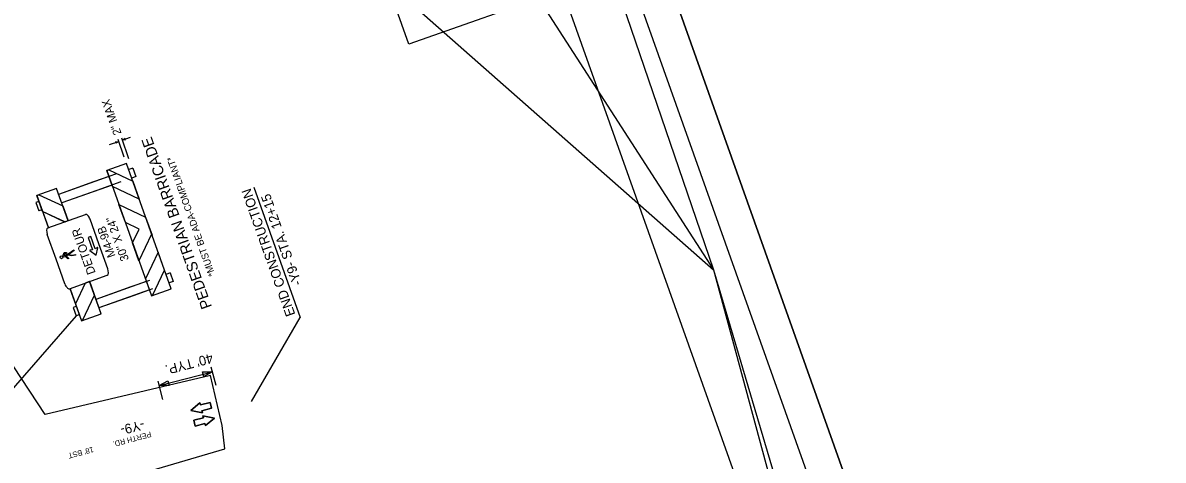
# Model space of a CAD drawing. Extents: x 1615843 to 1618439, y 899470 to 903922.
# Drawn here: x 1616617 to 1617445, y 902993 to 903311 of the extents above; entities that cross this region are included whole.
import ezdxf

# ---------------------------------------------------------------- set-up
doc = ezdxf.new("R2010")
doc.units = 0
for name, color, linetype in [('Default', 7, 'Continuous'), ('DEV BORDER CELL', 7, 'Continuous'), ('DEV DIRECTION OF TRAFFIC FLOW ARROW CELL', 7, 'Continuous'), ('DEV PED BARRICADE SECTION VIEW CELL', 7, 'Continuous'), ('GS M4-9b CELL', 7, 'Continuous'), ('Prop DSN Text', 7, 'Continuous'), ('Prop Horizontal Alignment Tick Label', 7, 'Continuous'), ('Scratch_Level_0', 7, 'Continuous'), ('Scratch_Level_5', 7, 'Continuous'), ('Sheet Clip Boundary CELL', 7, 'Continuous'), ('Sheet Plot Border Outside CELL', 7, 'Continuous'), ('Text', 7, 'Continuous')]:
    doc.layers.add(name, color=color, linetype=linetype)

msp = doc.modelspace()

# ---------------------------------------------------------------- linework, layer by layer
at = {"layer": 'Default'}
msp.add_line((1616655.34, 903097.86), (1616587.39, 903020.2), dxfattribs=at)
at = {"layer": 'DEV BORDER CELL'}
msp.add_lwpolyline([(1615874.87, 903538.12), (1616377.33, 902124.77), (1617366.67, 902476.49), (1616864.22, 903889.84)], close=True, dxfattribs=at)
at = {"layer": 'DEV DIRECTION OF TRAFFIC FLOW ARROW CELL'}
for p, q in [((1616745.15, 903034.59), (1616738.54, 903029.14)), ((1616738.54, 903029.14), (1616745.15, 903034.59)), ((1616738.54, 903029.14), (1616746.96, 903027.52)), ((1616746.96, 903027.52), (1616738.54, 903029.14)), ((1616745.52, 903033.16), (1616745.15, 903034.59)), ((1616745.15, 903034.59), (1616745.52, 903033.16)), ((1616752.49, 903034.95), (1616745.52, 903033.16)), ((1616745.52, 903033.16), (1616752.49, 903034.95)), ((1616746.59, 903028.95), (1616753.57, 903030.73)), ((1616753.57, 903030.73), (1616746.59, 903028.95)), ((1616746.96, 903027.52), (1616746.59, 903028.95)), ((1616746.59, 903028.95), (1616746.96, 903027.52)), ((1616753.57, 903030.73), (1616752.49, 903034.95)), ((1616752.49, 903034.95), (1616753.57, 903030.73)), ((1616747.67, 903023.85), (1616740.69, 903022.07)), ((1616740.69, 903022.07), (1616747.67, 903023.85)), ((1616740.69, 903022.07), (1616741.77, 903017.86)), ((1616741.77, 903017.86), (1616740.69, 903022.07)), ((1616741.77, 903017.86), (1616748.75, 903019.64)), ((1616748.75, 903019.64), (1616741.77, 903017.86)), ((1616755.72, 903023.67), (1616747.3, 903025.28)), ((1616747.3, 903025.28), (1616747.67, 903023.85)), ((1616747.67, 903023.85), (1616747.3, 903025.28)), ((1616747.3, 903025.28), (1616755.72, 903023.67)), ((1616748.75, 903019.64), (1616749.11, 903018.21)), ((1616749.11, 903018.21), (1616748.75, 903019.64)), ((1616749.11, 903018.21), (1616755.72, 903023.67)), ((1616755.72, 903023.67), (1616749.11, 903018.21))]:
    msp.add_line(p, q, dxfattribs=at)
at = {"layer": 'DEV PED BARRICADE SECTION VIEW CELL'}
for p, q in [((1616693.6, 903212.14), (1616688.33, 903226.96)), ((1616693.6, 903212.14), (1616688.33, 903226.96)), ((1616688.8, 903225.65), (1616694.79, 903227.78)), ((1616688.8, 903225.65), (1616694.79, 903227.78)), ((1616688.8, 903225.65), (1616690.81, 903226.99)), ((1616688.8, 903225.65), (1616690.81, 903226.99)), ((1616688.8, 903225.65), (1616690.81, 903226.99)), ((1616688.8, 903225.65), (1616690.81, 903226.99)), ((1616690.81, 903226.99), (1616690.45, 903226.24)), ((1616690.81, 903226.99), (1616690.45, 903226.24)), ((1616690.81, 903226.99), (1616690.45, 903226.24)), ((1616690.81, 903226.99), (1616690.45, 903226.24)), ((1616679.53, 903222.35), (1616686.16, 903224.71)), ((1616679.53, 903222.35), (1616686.16, 903224.71)), ((1616683.75, 903224.48), (1616686.16, 903224.71)), ((1616683.75, 903224.48), (1616686.16, 903224.71)), ((1616683.75, 903224.48), (1616686.16, 903224.71)), ((1616683.75, 903224.48), (1616686.16, 903224.71)), ((1616684.5, 903224.12), (1616683.75, 903224.48)), ((1616684.5, 903224.12), (1616683.75, 903224.48)), ((1616684.5, 903224.12), (1616683.75, 903224.48)), ((1616684.5, 903224.12), (1616683.75, 903224.48)), ((1616686.16, 903224.71), (1616684.14, 903223.37)), ((1616686.16, 903224.71), (1616684.14, 903223.37)), ((1616686.16, 903224.71), (1616684.14, 903223.37)), ((1616686.16, 903224.71), (1616684.14, 903223.37)), ((1616684.14, 903223.37), (1616684.5, 903224.12)), ((1616684.14, 903223.37), (1616684.5, 903224.12)), ((1616684.14, 903223.37), (1616684.5, 903224.12)), ((1616684.14, 903223.37), (1616684.5, 903224.12)), ((1616690.2, 903213.33), (1616685.69, 903226.02)), ((1616690.2, 903213.33), (1616685.69, 903226.02)), ((1616691.2, 903225.88), (1616688.8, 903225.65)), ((1616691.2, 903225.88), (1616688.8, 903225.65)), ((1616691.2, 903225.88), (1616688.8, 903225.65)), ((1616691.2, 903225.88), (1616688.8, 903225.65)), ((1616690.45, 903226.24), (1616691.2, 903225.88)), ((1616690.45, 903226.24), (1616691.2, 903225.88)), ((1616690.45, 903226.24), (1616691.2, 903225.88)), ((1616690.45, 903226.24), (1616691.2, 903225.88)), ((1616691.88, 903208.61), (1616677.58, 903203.53)), ((1616691.88, 903208.61), (1616677.58, 903203.53)), ((1616677.58, 903203.53), (1616709.98, 903112.41)), ((1616681.7, 903191.94), (1616677.58, 903203.53)), ((1616677.58, 903203.53), (1616709.98, 903112.41)), ((1616681.7, 903191.94), (1616677.58, 903203.53)), ((1616724.27, 903117.49), (1616691.88, 903208.61)), ((1616724.27, 903117.49), (1616691.88, 903208.61)), ((1616696.51, 903205.38), (1616693.42, 903204.28)), ((1616696.51, 903205.38), (1616693.42, 903204.28)), ((1616696.51, 903205.38), (1616698.71, 903199.19)), ((1616696.51, 903205.38), (1616698.71, 903199.19)), ((1616679.12, 903199.2), (1616642.55, 903186.2)), ((1616667.98, 903195.24), (1616642.55, 903186.2)), ((1616684.68, 903201.17), (1616667.98, 903195.24)), ((1616687.75, 903195.3), (1616670.18, 903189.05)), ((1616698.71, 903199.19), (1616695.62, 903198.09)), ((1616698.71, 903199.19), (1616695.62, 903198.09)), ((1616696.42, 903195.85), (1616701.08, 903182.73)), ((1616696.42, 903195.85), (1616701.08, 903182.73)), ((1616641.01, 903190.53), (1616626.71, 903185.45)), ((1616641.01, 903190.53), (1616626.71, 903185.45)), ((1616630.83, 903173.86), (1616626.71, 903185.45)), ((1616626.71, 903185.45), (1616635.1, 903161.86)), ((1616626.71, 903185.45), (1616635.14, 903161.74)), ((1616630.83, 903173.86), (1616626.71, 903185.45)), ((1616649.36, 903167.05), (1616641.01, 903190.53)), ((1616649.4, 903166.93), (1616641.01, 903190.53)), ((1616681.32, 903193.01), (1616644.75, 903180.01)), ((1616670.18, 903189.05), (1616644.75, 903180.01)), ((1616701.08, 903182.73), (1616681.7, 903191.94)), ((1616701.08, 903182.73), (1616681.7, 903191.94)), ((1616628.25, 903181.12), (1616626.03, 903180.32)), ((1616628.25, 903181.12), (1616626.03, 903180.32)), ((1616626.03, 903180.32), (1616628.23, 903174.14)), ((1616626.03, 903180.32), (1616628.23, 903174.14)), ((1616691.03, 903165.7), (1616686.37, 903178.82)), ((1616686.37, 903178.82), (1616705.74, 903169.61)), ((1616691.03, 903165.7), (1616686.37, 903178.82)), ((1616686.37, 903178.82), (1616705.74, 903169.61)), ((1616630.45, 903174.93), (1616628.23, 903174.14)), ((1616630.45, 903174.93), (1616628.23, 903174.14)), ((1616646.95, 903166.2), (1616630.83, 903173.86)), ((1616647.11, 903166.12), (1616630.83, 903173.86)), ((1616705.74, 903169.61), (1616710.41, 903156.49)), ((1616705.74, 903169.61), (1616710.41, 903156.49)), ((1616700.93, 903161), (1616691.03, 903165.7)), ((1616700.93, 903161), (1616691.03, 903165.7)), ((1616696.22, 903151.1), (1616700.93, 903161)), ((1616696.22, 903151.1), (1616700.93, 903161)), ((1616710.1, 903157.36), (1616700.89, 903137.98)), ((1616710.1, 903157.36), (1616700.89, 903137.98)), ((1616700.89, 903137.98), (1616696.22, 903151.1)), ((1616700.89, 903137.98), (1616696.22, 903151.1)), ((1616714.76, 903144.24), (1616705.55, 903124.86)), ((1616714.76, 903144.24), (1616705.55, 903124.86)), ((1616719.43, 903131.12), (1616714.76, 903144.24)), ((1616719.43, 903131.12), (1616714.76, 903144.24)), ((1616723.63, 903129.11), (1616720.53, 903128.01)), ((1616723.63, 903129.11), (1616720.53, 903128.01)), ((1616723.63, 903129.11), (1616725.83, 903122.92)), ((1616723.63, 903129.11), (1616725.83, 903122.92)), ((1616661.79, 903121.72), (1616654.68, 903106.78)), ((1616661.71, 903121.56), (1616654.68, 903106.78)), ((1616673.4, 903099.4), (1616665.06, 903122.88)), ((1616673.4, 903099.4), (1616665.1, 903122.77)), ((1616706.24, 903122.93), (1616669.66, 903109.92)), ((1616695.1, 903118.97), (1616669.66, 903109.92)), ((1616708.45, 903123.71), (1616695.1, 903118.97)), ((1616705.55, 903124.86), (1616709.98, 903112.41)), ((1616705.55, 903124.86), (1616709.98, 903112.41)), ((1616725.83, 903122.92), (1616722.73, 903121.82)), ((1616725.83, 903122.92), (1616722.73, 903121.82)), ((1616650.72, 903117.91), (1616659.11, 903094.32)), ((1616650.8, 903117.68), (1616659.11, 903094.32)), ((1616708.44, 903116.74), (1616671.86, 903103.74)), ((1616697.3, 903112.78), (1616671.86, 903103.74)), ((1616710.74, 903117.56), (1616697.3, 903112.78)), ((1616709.98, 903112.41), (1616724.27, 903117.49)), ((1616709.98, 903112.41), (1616724.27, 903117.49)), ((1616724.09, 903118), (1616723.76, 903117.31)), ((1616724.09, 903118), (1616723.76, 903117.31)), ((1616724.27, 903117.49), (1616724.09, 903118)), ((1616724.27, 903117.49), (1616724.09, 903118)), ((1616655.37, 903104.84), (1616653.14, 903104.05)), ((1616655.37, 903104.84), (1616653.14, 903104.05)), ((1616653.14, 903104.05), (1616655.34, 903097.86)), ((1616653.14, 903104.05), (1616655.34, 903097.86)), ((1616654.68, 903106.78), (1616659.11, 903094.32)), ((1616654.68, 903106.78), (1616659.11, 903094.32)), ((1616657.57, 903098.65), (1616655.34, 903097.86)), ((1616657.57, 903098.65), (1616655.34, 903097.86)), ((1616659.11, 903094.32), (1616673.4, 903099.4)), ((1616659.11, 903094.32), (1616673.4, 903099.4)), ((1616673.22, 903099.91), (1616672.89, 903099.22)), ((1616673.22, 903099.91), (1616672.89, 903099.22)), ((1616673.4, 903099.4), (1616673.22, 903099.91)), ((1616673.4, 903099.4), (1616673.22, 903099.91))]:
    msp.add_line(p, q, dxfattribs=at)
for points in [[(1616677.58, 903203.53), (1616679.11, 903204.08), (1616696.42, 903195.85)], [(1616677.58, 903203.53), (1616679.11, 903204.08), (1616696.42, 903195.85)], [(1616626.71, 903185.45), (1616628.24, 903185.99), (1616645.55, 903177.77)], [(1616626.71, 903185.45), (1616628.24, 903185.99), (1616645.55, 903177.77)], [(1616645.55, 903177.77), (1616649.36, 903167.05), (1616646.95, 903166.2)], [(1616645.55, 903177.77), (1616649.4, 903166.93), (1616647.11, 903166.12)], [(1616709.98, 903112.41), (1616710.64, 903112.64), (1616719.43, 903131.12)], [(1616709.98, 903112.41), (1616710.64, 903112.64), (1616719.43, 903131.12)], [(1616668.56, 903113.03), (1616665.1, 903122.77), (1616661.71, 903121.56)], [(1616668.56, 903113.03), (1616665.06, 903122.88), (1616661.79, 903121.72)], [(1616659.11, 903094.32), (1616659.77, 903094.56), (1616668.56, 903113.03)], [(1616659.11, 903094.32), (1616659.77, 903094.56), (1616668.56, 903113.03)]]:
    msp.add_lwpolyline(points, dxfattribs=at)
at = {"layer": 'GS M4-9b CELL'}
for p, q in [((1616665.95, 903155.49), (1616664.08, 903154.83)), ((1616664.08, 903154.83), (1616667.25, 903145.94)), ((1616669.13, 903146.54), (1616665.95, 903155.49)), ((1616649.53, 903142.98), (1616653.46, 903145.9)), ((1616653.84, 903145.4), (1616650.04, 903142.58)), ((1616653.46, 903145.9), (1616653.84, 903145.4)), ((1616665.26, 903145.39), (1616669.71, 903142)), ((1616667.25, 903145.94), (1616665.34, 903145.73)), ((1616670.86, 903147.65), (1616669.13, 903146.54)), ((1616669.71, 903142), (1616671.12, 903147.43)), ((1616646.18, 903140.7), (1616645.7, 903141.36)), ((1616649.34, 903142.07), (1616647.29, 903141.16)), ((1616650.01, 903139.7), (1616649.29, 903139.44)), ((1616652.13, 903141.47), (1616649.34, 903142.07)), ((1616650.04, 903142.58), (1616652.16, 903142.13)), ((1616654.91, 903141.91), (1616652.13, 903141.47)), ((1616652.16, 903142.13), (1616654.81, 903142.54)), ((1616654.81, 903142.54), (1616654.91, 903141.91))]:
    msp.add_line(p, q, dxfattribs=at)
for points in [[(1616634.65, 903161.82), (1616662.11, 903171.59)], [(1616671.78, 903150.15), (1616665.39, 903168.11)], [(1616640.68, 903139.09), (1616634.3, 903157.05)], [(1616645.7, 903141.36), (1616646.48, 903143.86), (1616648.3, 903143.93), (1616648.33, 903143.31), (1616646.94, 903143.25), (1616646.5, 903141.85), (1616649.53, 903142.98)], [(1616678.16, 903132.19), (1616671.78, 903150.15)], [(1616647.07, 903121.13), (1616640.68, 903139.09)], [(1616649.29, 903139.44), (1616647.97, 903140.58), (1616646.18, 903140.7)], [(1616647.29, 903141.16), (1616648.41, 903141.08), (1616650.01, 903139.7)], [(1616650.35, 903117.65), (1616677.81, 903127.42)]]:
    msp.add_lwpolyline(points, dxfattribs=at)
msp.add_circle((1616644.62, 903140.49), 1.02, dxfattribs=at)
for centre, start, end in [((1616665.36, 903145.54), 97.00101, 235.6629), ((1616670.95, 903147.48), 343.47847, 122.14036)]:
    msp.add_arc(centre, 0.182, start, end, dxfattribs=at)
for centre, major_axis, start_param, end_param in [((1616663.58, 903167.46), (1.47, -4.12), 1.570796, 3.141593), ((1616636.11, 903157.7), (-1.47, 4.12), 0, 1.570796), ((1616676.35, 903131.54), (1.47, -4.12), 0, 1.570796), ((1616648.88, 903121.78), (1.47, -4.12), 4.712162, 6.283185)]:
    msp.add_ellipse(centre, major_axis=major_axis, ratio=0.44, start_param=start_param, end_param=end_param, dxfattribs=at)
at = {"layer": 'Prop DSN Text'}
for p in [(1616784.38, 903191.49), (1616782.73, 903035.77)]:
    msp.add_line(p, (1616818.07, 903096.71), dxfattribs=at)
at = {"layer": 'Scratch_Level_0'}
msp.add_lwpolyline([(1615938.73, 903507.75), (1616407.69, 902188.63), (1617302.81, 902506.85), (1617008.42, 903334.93), (1616896.98, 903295.32), (1616722.42, 903786.36)], close=True, dxfattribs=at)
at = {"layer": 'Scratch_Level_5'}
for points in [[(1616347.43, 902358.15), (1615993.9, 903352.57), (1616755.41, 903693.55), (1617118.27, 903131.4), (1617302.81, 902506.85), (1616959.09, 902384.66)], [(1616705.54, 902373.67), (1616699.85, 902458.96), (1616686.62, 902573.2), (1616667.04, 902687.93), (1616638.01, 902809.43), (1616596.83, 902943.32), (1616588.98, 902949.04), (1616499.35, 903201.92), (1616504.06, 903203.6), (1616506.92, 903204.49), (1616400, 903496.37), (1616388.07, 903529.07), (1616755.41, 903693.55), (1617118.27, 903131.4), (1617302.81, 902506.85), (1616959.09, 902384.66)], [(1616699.32, 902373.4), (1616633.77, 902806.46), (1616631.94, 902813.22), (1616597.93, 902897.46), (1616599.33, 902920.4), (1616597.1, 902927.03), (1616370.6, 903502.2), (1616643.52, 903550.34), (1617118.27, 903131.4), (1617302.81, 902506.85), (1616959.09, 902384.66)]]:
    msp.add_lwpolyline(points, close=True, dxfattribs=at)
at = {"layer": 'Sheet Clip Boundary CELL'}
for points in [[(1616920.55, 902382.99), (1616489.91, 902364.33), (1616361.78, 902925.96), (1616113.49, 903406.12), (1616903.33, 903759.78), (1617118.27, 903131.4), (1617236.29, 902693.96), (1617083.45, 902390.05)], [(1616694.55, 902373.19), (1616732.15, 902374.79), (1616717.45, 902614.43), (1616639.68, 902965.04), (1616763.33, 903001.21), (1616761.22, 903018.27), (1616752.73, 903054.64), (1616632.71, 903026.28), (1616564.32, 903130.19), (1616414.61, 903540.98), (1616374.17, 903522.92), (1616456.37, 903298.56), (1616566.89, 902980.98), (1616598.23, 902894.85), (1616630.48, 902783.84), (1616648.21, 902701.52), (1616669.68, 902592.43), (1616683.11, 902510.03), (1616690.19, 902449.56), (1616690.27, 902434.92)]]:
    msp.add_lwpolyline(points, close=True, dxfattribs=at)
at = {"layer": 'Sheet Plot Border Outside CELL'}
for points in [[(1617444.82, 902331.28), (1616879.4, 903921.77), (1615842.94, 903553.3), (1616408.37, 901962.82)], [(1617444.82, 902331.28), (1616408.37, 901962.82), (1615842.94, 903553.3), (1616879.4, 903921.77)]]:
    msp.add_lwpolyline(points, close=True, dxfattribs=at)
at = {"layer": 'Text'}
for p, q in [((1616756.92, 903047.23), (1616753.43, 903060.64)), ((1616715.6, 903047.19), (1616754.31, 903057.25)), ((1616718.21, 903037.16), (1616714.72, 903050.57))]:
    msp.add_line(p, q, dxfattribs=at)
for points in [[(1616747.1, 903057.19), (1616754.31, 903057.25), (1616747.98, 903053.8)], [(1616722.82, 903047.25), (1616715.6, 903047.19), (1616721.93, 903050.64)]]:
    msp.add_lwpolyline(points, close=True, dxfattribs=at)

# ---------------------------------------------------------------- texts
at = {"layer": 'Default'}
for s, p in [('PERTH RD.', (1616709.28, 903013.9)), ("18' BST", (1616667.35, 903002.82))]:
    msp.add_text(s, height=4, rotation=194.92604, dxfattribs=at).set_placement(p)
at = {"layer": 'DEV PED BARRICADE SECTION VIEW CELL'}
for s, height, p in [('2" MAX', 6, (1616688.32, 903230.53)), ('PEDESTRIAN BARRICADE', 7.8816, (1616754.03, 903104.56)), ('*MUST BE ADA-COMPLIANT*', 5, (1616756.35, 903127.67))]:
    msp.add_text(s, height=height, rotation=109.57069, dxfattribs=at).set_placement(p)
at = {"layer": 'GS M4-9b CELL'}
for s, height, p in [("30'' X 24''", 6, (1616693.68, 903138.88)), ('DETOUR', 6.217, (1616669.49, 903129.25)), ('M4-9B', 6, (1616683.94, 903141.51))]:
    msp.add_text(s, height=height, rotation=109.57069, dxfattribs=at).set_placement(p)
at = {"layer": 'Prop DSN Text'}
for s, p in [('END CONSTRUCTION', (1616814.54, 903098.99)), ('-Y9- STA. 12+15', (1616819.33, 903121.35))]:
    msp.add_text(s, height=7, rotation=109.57065, dxfattribs=at).set_placement(p)
at = {"layer": 'Prop Horizontal Alignment Tick Label'}
msp.add_text('-Y9-', height=7, rotation=194.08312, dxfattribs=at).set_placement((1616703.93, 903022.31))
at = {"layer": 'Text'}
msp.add_text("40' TYP.", height=7, rotation=194.57758, dxfattribs=at).set_placement((1616753.71, 903070.74))

doc.saveas('drawing.dxf')
